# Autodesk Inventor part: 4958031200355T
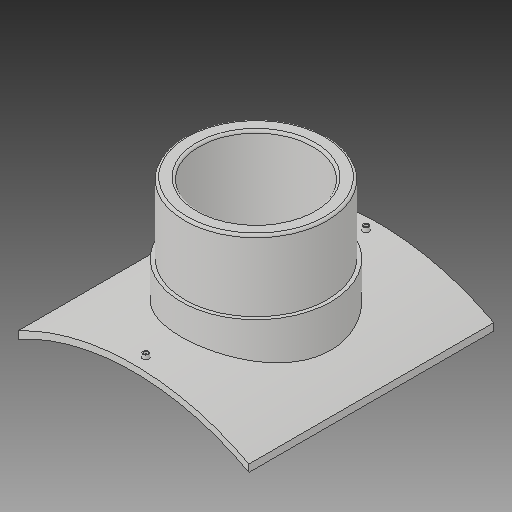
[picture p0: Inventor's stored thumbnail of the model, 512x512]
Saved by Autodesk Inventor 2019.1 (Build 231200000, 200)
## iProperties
Created: 2017-10
Part Number: 4958031200355T
Material: Generic
Description: PLASSON BRANCH SADDLE  1200x355
Document SubType Name: Modeling
Designer: KIM
Mass: 2754.05 g
Surface Area: 3037.44 cm^2
Volume: 2754.05 cm^3
Density: 1 g/cm^3
Appearance: Default
Author: KIM
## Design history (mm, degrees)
derived "495803.ipt"
feature "Solid1::495803.ipt"
tag "TaggingFeature1"
body "Solid1"
other parameters: "d1" = 16, "d2" = 575, "d4" = 0, "d12" = 625.6, "d13" = 14, "d14" = 274.5, "d16" = 5 deg, "d18" = 4, "d19" = 14, "d20" = 0, "d21" = 3, "d22" = 0, "d23" = 868, "d24" = 372.75, "d25" = 16, "d26" = 284, "d28" = 0, "d29" = 9.6, "d31" = 0, "d32" = 126, "d33" = 0, "d34" = 12, "d36" = 355, "d37" = 176.4, "d38" = 0, "d39" = 6, "d_1" = 355, "B_" = 575, "H_" = 252, "x_" = 16, "D_" = 16
